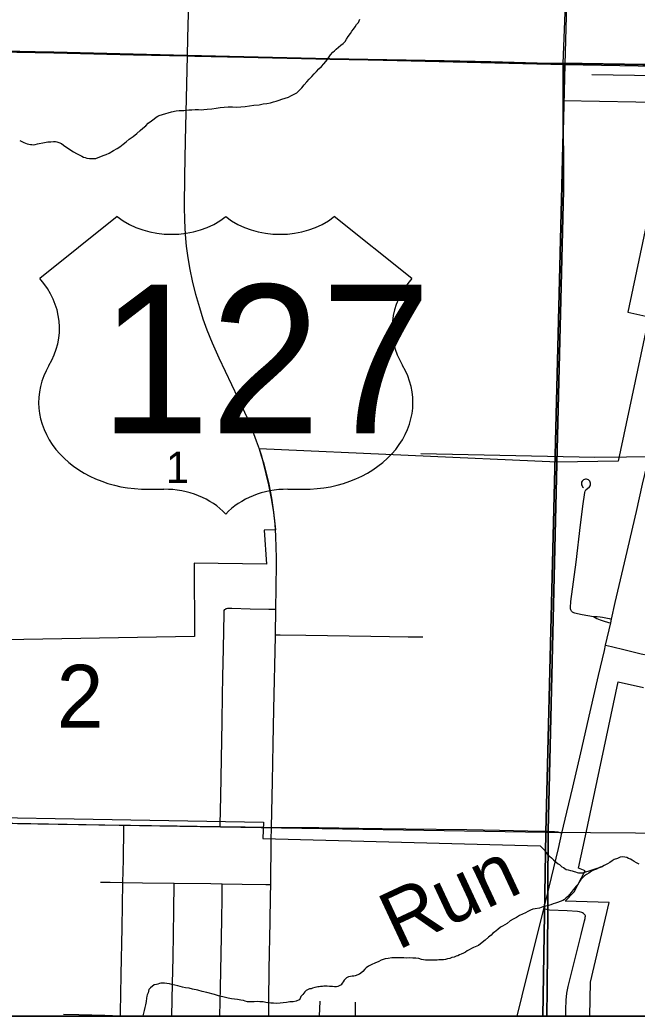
# Model space of a CAD drawing. Extents: x 2.4 to 73.1, y 4.5 to 25.6.
# Drawn here: x 30.055 to 30.465, y 17.985 to 18.648 of the extents above; entities that cross this region are included whole.
import ezdxf

# ---------------------------------------------------------------- set-up
doc = ezdxf.new("R2010")
doc.units = 0
for name, color, linetype in [('GM_X_City_Street', 7, 'Continuous'), ('GM_X_Corporation', 7, 'Continuous'), ('GM_X_County_Road', 7, 'Continuous'), ('GM_X_Interchange_Ramps', 7, 'Continuous'), ('GM_X_Minor_Lake_Text', 7, 'Continuous'), ('GM_X_Minor_River', 7, 'Continuous'), ('GM_X_Section', 7, 'Continuous'), ('GM_X_Section_Text', 7, 'Continuous'), ('GM_X_State_Route', 7, 'Continuous'), ('GM_X_Township', 7, 'Continuous'), ('GM_X_Township_Road', 7, 'Continuous'), ('GM_X_US_Location', 7, 'Continuous'), ('GM_X_US_Route', 7, 'Continuous'), ('GM_X_US_Shield', 7, 'Continuous'), ('SH_Cut_Line', 7, 'Continuous'), ('SH_Data', 7, 'Continuous')]:
    doc.layers.add(name, color=color, linetype=linetype)

msp = doc.modelspace()

# ---------------------------------------------------------------- linework, layer by layer
at = {"layer": 'GM_X_City_Street'}
msp.add_line((30.25423, 17.98522), (30.25469, 17.99511), dxfattribs=at)
for points in [[(30.22492, 18.23874), (30.22801, 18.23869), (30.24502, 18.23843), (30.28833, 18.23777), (30.31308, 18.23744), (30.31926, 18.23746), (30.32297, 18.2375)], [(30.1219, 17.98541), (30.12195, 17.98798), (30.12215, 17.99963), (30.12239, 18.01287), (30.12298, 18.044), (30.12345, 18.07399), (30.12383, 18.08914), (30.12413, 18.11017), (30.12416, 18.11215)], [(30.10852, 18.07435), (30.11513, 18.07422), (30.12345, 18.07399), (30.13663, 18.07375), (30.15751, 18.07349), (30.18191, 18.0733), (30.18958, 18.07321), (30.20277, 18.07302), (30.21857, 18.07279), (30.22175, 18.07275)], [(30.1561, 17.98522), (30.15657, 18.00694), (30.15681, 18.02407), (30.15747, 18.05518), (30.15751, 18.07349)], [(30.18797, 17.98522), (30.18797, 17.98527), (30.18829, 18.00397), (30.18921, 18.04913), (30.18944, 18.06393), (30.18958, 18.07321)], [(30.41797, 17.98522), (30.41805, 17.98956), (30.41822, 17.99576), (30.41867, 18.00038), (30.41948, 18.00496), (30.42823, 18.03952), (30.4304, 18.04856), (30.43074, 18.05003), (30.4309, 18.05115), (30.43093, 18.05148), (30.43092, 18.05179), (30.4308, 18.05229), (30.43063, 18.05263), (30.43041, 18.05287), (30.4298, 18.05342), (30.42908, 18.05384), (30.4285, 18.05412), (30.42709, 18.05458), (30.42561, 18.05483), (30.41886, 18.05521), (30.40699, 18.05575), (30.40611, 18.05586), (30.40502, 18.05605), (30.40338, 18.05649)], [(30.27803, 17.98522), (30.27804, 17.98962), (30.27802, 17.99438)], [(30.08403, 17.98647), (30.09415, 17.98621), (30.11139, 17.98578), (30.1219, 17.98541), (30.12739, 17.98522)]]:
    msp.add_lwpolyline(points, dxfattribs=at)
at = {"layer": 'GM_X_Corporation'}
for points in [[(30.48071, 18.6179), (30.45695, 18.61824), (30.42882, 18.61865), (30.41612, 18.61875), (30.4162, 18.59398), (30.48874, 18.59276), (30.45921, 18.45328), (30.47306, 18.45009), (30.45278, 18.35426), (30.41211, 18.35353), (30.21409, 18.36248), (30.21556, 18.35786), (30.21641, 18.35521), (30.21695, 18.35328), (30.21869, 18.34615), (30.22042, 18.33883), (30.22222, 18.32961), (30.22367, 18.32033), (30.22457, 18.31256), (30.22484, 18.30853), (30.21749, 18.3083), (30.21891, 18.28563), (30.17097, 18.28643), (30.17102, 18.23759), (30.03215, 18.23516)], [(30.0279, 17.98522), (30.434, 17.98522), (30.4344, 18.00767), (30.44687, 18.06076), (30.4176, 18.06153), (30.42345, 18.06781), (30.43082, 18.0817), (30.42643, 18.08348), (30.431, 18.10507), (30.45269, 18.20758), (30.4695, 18.20371)]]:
    msp.add_lwpolyline(points, dxfattribs=at)
at = {"layer": 'GM_X_County_Road'}
msp.add_line((30.44442, 18.23188), (30.44778, 18.24662), dxfattribs=at)
for points in [[(30.44778, 18.24662), (30.44836, 18.24915), (30.45086, 18.26013), (30.45782, 18.29042), (30.46485, 18.32069), (30.46894, 18.33889), (30.47334, 18.35731), (30.47396, 18.35999)], [(30.41537, 18.10676), (30.41868, 18.12084), (30.42252, 18.1375), (30.42794, 18.16016), (30.43411, 18.18745), (30.43973, 18.21166), (30.44361, 18.22831), (30.44442, 18.23188)], [(29.99456, 18.11418), (30.00252, 18.11405), (30.0134, 18.11395), (30.03829, 18.11363), (30.07407, 18.11307), (30.12416, 18.11215)], [(30.12416, 18.11215), (30.1285, 18.11207), (30.1425, 18.11193), (30.15961, 18.11162), (30.18606, 18.11139), (30.18817, 18.11135)], [(30.18817, 18.11135), (30.20472, 18.11103), (30.21561, 18.11092), (30.21717, 18.11086), (30.22234, 18.11068)], [(30.40338, 18.05649), (30.40618, 18.06806), (30.40688, 18.07094), (30.413, 18.09663), (30.41537, 18.10676)], [(30.38559, 17.98522), (30.3923, 18.01211), (30.39872, 18.03773), (30.40338, 18.05649)]]:
    msp.add_lwpolyline(points, dxfattribs=at)
at = {"layer": 'GM_X_Interchange_Ramps'}
for points in [[(29.49738, 21.67933), (29.49738, 18.64027), (29.51045, 18.6399), (29.59434, 18.63772), (29.6596, 18.63611), (29.71864, 18.63468), (29.75282, 18.63393), (29.80409, 18.63267), (29.84759, 18.63174), (29.91284, 18.62996), (30.01539, 18.62763), (30.04024, 18.62677), (30.07753, 18.62611), (30.13036, 18.62476), (30.1663, 18.62397), (30.17131, 18.62386), (30.20382, 18.62314), (30.26115, 18.6218), (30.33704, 18.62041), (30.36807, 18.61966), (30.40672, 18.61876), (30.41612, 18.61875), (30.43582, 19.1212)], [(29.49738, 17.98522), (30.40528, 17.98522), (30.40547, 18.0034), (30.40599, 18.05614), (30.40606, 18.06834), (30.40631, 18.10839), (30.4123, 18.36171), (30.41639, 18.53419), (30.4162, 18.59398), (30.41612, 18.61875), (30.40672, 18.61876), (30.36807, 18.61966), (30.33704, 18.62041), (30.26115, 18.6218), (30.20382, 18.62314), (30.17131, 18.62386), (30.1663, 18.62397), (30.13036, 18.62476), (30.07753, 18.62611), (30.04024, 18.62677)], [(30.48071, 18.6179), (30.45695, 18.61824), (30.42882, 18.61865), (30.41612, 18.61875), (30.4162, 18.59398), (30.41639, 18.53419), (30.4123, 18.36171), (30.40631, 18.10839), (30.40606, 18.06834), (30.40599, 18.05614), (30.40547, 18.0034), (30.40528, 17.98522), (33.45306, 17.98522)]]:
    msp.add_lwpolyline(points, dxfattribs=at)
at = {"layer": 'GM_X_Minor_River'}
for points in [[(30.14975, 18.58474), (30.15588, 18.5865), (30.15894, 18.58719), (30.16084, 18.58733), (30.16236, 18.5873), (30.16407, 18.58745), (30.16579, 18.5876), (30.16731, 18.58776), (30.16941, 18.5879), (30.1715, 18.58804), (30.17378, 18.58799), (30.17549, 18.58795), (30.1774, 18.5881), (30.17949, 18.58824), (30.18273, 18.58855), (30.1854, 18.58887), (30.18807, 18.58938), (30.19074, 18.5897), (30.19359, 18.58982), (30.19625, 18.58976), (30.1991, 18.5897), (30.20196, 18.58982), (30.20482, 18.59014), (30.20768, 18.59045), (30.21054, 18.59096), (30.21416, 18.59125), (30.21683, 18.59176), (30.21912, 18.59209), (30.2216, 18.59261), (30.22352, 18.59313), (30.22543, 18.59366), (30.22735, 18.59438), (30.22926, 18.5949), (30.23137, 18.59561), (30.23348, 18.59632), (30.2352, 18.59705), (30.23694, 18.59815), (30.23905, 18.59924), (30.24061, 18.60072), (30.24236, 18.60258), (30.24392, 18.60445), (30.24568, 18.60649), (30.24743, 18.60835), (30.24918, 18.61002), (30.25074, 18.6117), (30.2523, 18.61337), (30.25386, 18.61505), (30.25542, 18.61672), (30.25717, 18.61839), (30.25834, 18.61988), (30.25932, 18.62119), (30.26148, 18.62437), (30.26305, 18.62623), (30.26421, 18.62716), (30.26537, 18.62827), (30.26692, 18.62956), (30.26828, 18.63086), (30.27002, 18.63196), (30.27119, 18.63327), (30.27217, 18.63476), (30.27336, 18.63663), (30.27473, 18.6385), (30.27572, 18.64019), (30.2767, 18.6415), (30.27787, 18.64299), (30.27886, 18.64449), (30.28003, 18.64598), (30.28103, 18.64805)], [(30.43533, 18.61131), (31.49498, 18.59472)], [(30.05488, 18.5675), (30.05639, 18.56671), (30.0577, 18.56611), (30.05864, 18.56571), (30.05978, 18.56531), (30.06091, 18.56509), (30.06205, 18.56488), (30.063, 18.56485), (30.06413, 18.56464), (30.06509, 18.56481), (30.06662, 18.56534), (30.07139, 18.56618), (30.07349, 18.56652), (30.07558, 18.56666), (30.0773, 18.56681), (30.07863, 18.56678), (30.07958, 18.56657), (30.0809, 18.56616), (30.08259, 18.56536), (30.08409, 18.56438), (30.08558, 18.5632), (30.08727, 18.56203), (30.08896, 18.56104), (30.09064, 18.55986), (30.09271, 18.55886), (30.0944, 18.55788), (30.09609, 18.55708), (30.09741, 18.55648), (30.09835, 18.55608), (30.09948, 18.55567), (30.10138, 18.55544), (30.1029, 18.55541), (30.10442, 18.55556), (30.10556, 18.55554), (30.10709, 18.55607), (30.10882, 18.55679), (30.11036, 18.55752), (30.11228, 18.55823), (30.11439, 18.55913), (30.11728, 18.56078), (30.11959, 18.56206), (30.12152, 18.56334), (30.12365, 18.565), (30.12558, 18.56648), (30.12771, 18.56833), (30.13023, 18.57017), (30.13274, 18.5722), (30.13487, 18.57406), (30.13681, 18.57572), (30.13875, 18.5772), (30.14031, 18.57906), (30.14244, 18.58053), (30.14418, 18.58182), (30.14553, 18.58293), (30.14669, 18.58366), (30.14765, 18.58402), (30.14975, 18.58474)], [(30.32148, 18.35921), (30.43721, 18.35696), (30.68973, 18.35957), (30.7177, 18.31848), (30.77838, 18.31995), (30.82527, 18.29172), (30.87479, 18.30408), (30.90304, 18.31768), (30.91765, 18.32222)], [(29.91477, 18.1194), (30.21692, 18.1141), (30.21649, 18.10329), (30.40097, 18.09835)], [(30.40097, 18.09835), (30.40376, 18.09563), (30.40579, 18.09273), (30.40728, 18.09137), (30.4084, 18.09039), (30.4097, 18.08903), (30.41156, 18.08747), (30.41287, 18.08649), (30.41381, 18.0859), (30.4153, 18.08454), (30.41642, 18.08394), (30.41811, 18.08276), (30.41944, 18.08254), (30.42113, 18.08193), (30.42227, 18.08172), (30.4234, 18.08131), (30.42435, 18.0811), (30.42548, 18.0807), (30.42642, 18.08049), (30.42794, 18.08045), (30.42927, 18.08042), (30.4423, 18.08468)], [(30.46667, 18.08622), (30.46498, 18.08721), (30.46347, 18.088), (30.46216, 18.08879), (30.46104, 18.08957), (30.45972, 18.08998), (30.4584, 18.09058), (30.45726, 18.0908), (30.45556, 18.09103), (30.45403, 18.09087), (30.4523, 18.08996), (30.45019, 18.08925), (30.44865, 18.08834), (30.44711, 18.08742), (30.44557, 18.08651), (30.44441, 18.08577), (30.44345, 18.08542), (30.4423, 18.08468)], [(30.4423, 18.08468), (30.44076, 18.08415), (30.43826, 18.08288), (30.43712, 18.08252), (30.43596, 18.08198), (30.435, 18.08162), (30.43326, 18.08033), (30.43172, 18.07941), (30.43037, 18.0785), (30.42784, 18.07608), (30.42666, 18.07402), (30.42587, 18.07271), (30.42489, 18.07159), (30.42392, 18.07048), (30.42275, 18.06917), (30.42157, 18.06749), (30.42039, 18.066), (30.41922, 18.0647), (30.41806, 18.06358), (30.41709, 18.06284), (30.41593, 18.06211), (30.41421, 18.06139), (30.41248, 18.06067), (30.41114, 18.06032), (30.40961, 18.05979), (30.40807, 18.05925), (30.40635, 18.05872), (30.40463, 18.05838), (30.40272, 18.05785), (30.40042, 18.05696), (30.39756, 18.05664), (30.39603, 18.0563), (30.3945, 18.05557), (30.39277, 18.05485), (30.39104, 18.05394), (30.38912, 18.05303), (30.38719, 18.05213), (30.38507, 18.05085), (30.38296, 18.04976), (30.38103, 18.04847), (30.3789, 18.04681), (30.37582, 18.04498), (30.37447, 18.04425), (30.37273, 18.04277), (30.37156, 18.04185), (30.3706, 18.04111), (30.36944, 18.04038), (30.36827, 18.03907), (30.36653, 18.03759), (30.36439, 18.03574), (30.36226, 18.03408), (30.35994, 18.03223), (30.35764, 18.03134), (30.35649, 18.03079), (30.35244, 18.02861), (30.35128, 18.02768), (30.34994, 18.02695), (30.3484, 18.02642), (30.34725, 18.02588), (30.3461, 18.02533), (30.34514, 18.02497), (30.3438, 18.02443), (30.34208, 18.02409), (30.34093, 18.02355), (30.3394, 18.0232), (30.33787, 18.02286), (30.33653, 18.0227), (30.33539, 18.02254), (30.33444, 18.02256), (30.33349, 18.02258), (30.33234, 18.02241), (30.33082, 18.02245), (30.3295, 18.02248), (30.32816, 18.02232), (30.32683, 18.02235), (30.32588, 18.02237), (30.32474, 18.0224), (30.32341, 18.02262), (30.3219, 18.02284), (30.3202, 18.02345), (30.3183, 18.02368), (30.31621, 18.02373), (30.31375, 18.02398), (30.31203, 18.02382), (30.31032, 18.02386), (30.3088, 18.0239), (30.30728, 18.02393), (30.305, 18.02398), (30.30234, 18.02385), (30.29986, 18.02353), (30.29795, 18.02319), (30.29642, 18.02285), (30.29528, 18.0225), (30.29354, 18.02158), (30.29105, 18.0205), (30.28893, 18.01941), (30.28682, 18.01832), (30.28528, 18.0174), (30.2843, 18.01648), (30.28294, 18.0148), (30.28177, 18.01368)], [(30.28177, 18.01368), (30.28081, 18.01314), (30.27793, 18.01187), (30.27697, 18.0117), (30.27602, 18.01172), (30.27488, 18.01156), (30.27354, 18.0114), (30.2722, 18.01067), (30.27064, 18.009), (30.26986, 18.00807), (30.26927, 18.00713), (30.26867, 18.006), (30.26771, 18.00546), (30.26636, 18.00492), (30.26541, 18.00475), (30.26427, 18.00477), (30.26275, 18.00481), (30.26085, 18.00485), (30.25933, 18.00507), (30.25838, 18.0051), (30.25705, 18.00513), (30.2561, 18.00496), (30.25496, 18.00479), (30.254, 18.00463), (30.25305, 18.00465), (30.2521, 18.00448), (30.25114, 18.00431), (30.24961, 18.00378), (30.24865, 18.00342), (30.24751, 18.00325), (30.24539, 18.00216), (30.24442, 18.00124), (30.24305, 17.99956), (30.24188, 17.99825), (30.24128, 17.99694), (30.24069, 17.996), (30.23877, 17.99509), (30.23667, 17.99476), (30.23458, 17.99462), (30.23229, 17.99429), (30.22581, 17.99368), (30.22372, 17.99373), (30.22182, 17.99377), (30.21992, 17.994), (30.21841, 17.99423), (30.21671, 17.99464), (30.21443, 17.9947), (30.21272, 17.99492), (30.21082, 17.99478), (30.20948, 17.99462), (30.20853, 17.99464), (30.20739, 17.99466), (30.20644, 17.99469), (30.20474, 17.9951), (30.20361, 17.99551), (30.2019, 17.99574), (30.19963, 17.99617), (30.19774, 17.9964), (30.19565, 17.99664), (30.19357, 17.99707), (30.19168, 17.99749), (30.18714, 17.99873), (30.1845, 17.99955), (30.1792, 18.00081), (30.17618, 18.00164), (30.17335, 18.00246), (30.16975, 18.00311), (30.16748, 18.00373), (30.16521, 18.00397), (30.16313, 18.0044), (30.16161, 18.00482), (30.15991, 18.00523), (30.15802, 18.00566), (30.15613, 18.00627), (30.15443, 18.00669), (30.15273, 18.00691), (30.15121, 18.00714), (30.14988, 18.00717), (30.14874, 18.007), (30.14778, 18.00684), (30.14682, 18.00648), (30.14587, 18.00631), (30.14434, 18.00596), (30.14182, 18.00393), (30.14066, 18.00282), (30.14023, 18.00074), (30.13963, 17.99942), (30.13942, 17.99848), (30.1392, 17.99715), (30.13896, 17.99488), (30.13853, 17.99261), (30.13811, 17.99091), (30.13769, 17.98902), (30.13726, 17.98713), (30.13685, 17.98543), (30.13681, 17.98522)]]:
    msp.add_lwpolyline(points, dxfattribs=at)
at = {"layer": 'GM_X_Section'}
for points in [[(29.92965, 19.13465), (30.43117, 19.12128), (30.41719, 18.61809), (29.91527, 18.62994)], [(30.86803, 19.11145), (30.43117, 19.12128), (30.41719, 18.61809), (30.9167, 18.60894), (30.95137, 18.60852), (30.95403, 18.77027), (30.86803, 18.77027)], [(29.91527, 18.62994), (30.41719, 18.61809), (30.40456, 18.10728), (29.90446, 18.11549)], [(30.9167, 18.60894), (30.91045, 18.10349), (30.40456, 18.10728), (30.41719, 18.61809)]]:
    msp.add_lwpolyline(points, close=True, dxfattribs=at)
at = {"layer": 'GM_X_State_Route'}
msp.add_line((30.22492, 18.23874), (30.2252, 18.25576), dxfattribs=at)
for points in [[(30.16642, 18.6237), (30.16663, 18.63553), (30.16795, 18.68526), (30.16868, 18.70546), (30.17039, 18.77073), (30.17181, 18.8189), (30.17292, 18.85619), (30.17375, 18.88727), (30.17457, 18.91836), (30.17747, 19.01781), (30.17859, 19.0551), (30.17994, 19.10328), (30.18067, 19.12692)], [(30.21421, 18.3622), (30.21239, 18.3675), (30.20965, 18.37476), (30.20603, 18.38333), (30.20017, 18.39602), (30.18755, 18.42274), (30.18312, 18.43269), (30.17958, 18.44134), (30.17692, 18.44866), (30.17456, 18.45608), (30.17202, 18.46507), (30.16978, 18.47414), (30.1682, 18.48177), (30.1669, 18.48945), (30.16589, 18.49718), (30.16518, 18.50494), (30.16467, 18.51427), (30.16448, 18.52361), (30.16458, 18.54383), (30.16512, 18.56714), (30.16642, 18.6237)], [(30.22496, 18.30825), (30.22469, 18.31228), (30.22379, 18.32005), (30.22233, 18.32934), (30.22054, 18.33856), (30.2188, 18.34587), (30.21706, 18.353), (30.21653, 18.35493), (30.21568, 18.35758), (30.21421, 18.3622)], [(30.2252, 18.25576), (30.2253, 18.27004), (30.22544, 18.27283), (30.22557, 18.28316), (30.22559, 18.29028), (30.22546, 18.29666), (30.22522, 18.30448), (30.22496, 18.30825)], [(30.22234, 18.11068), (30.22258, 18.12095), (30.223, 18.14118), (30.2235, 18.16606), (30.22389, 18.1894), (30.22491, 18.23762), (30.22492, 18.23874)], [(30.22175, 18.07275), (30.22215, 18.10229), (30.22234, 18.11068)], [(30.22084, 18.0164), (30.22135, 18.04784), (30.22164, 18.06495), (30.22175, 18.07275)], [(30.22056, 17.98522), (30.22049, 17.99494), (30.22084, 18.0164)]]:
    msp.add_lwpolyline(points, dxfattribs=at)
at = {"layer": 'GM_X_Township'}
msp.add_lwpolyline([(30.92238, 18.60883), (30.91795, 18.60896), (30.91319, 18.60918), (30.88149, 18.60963), (30.84568, 18.61038), (30.79587, 18.6118), (30.77562, 18.61225), (30.71802, 18.61361), (30.68042, 18.61425), (30.66974, 18.61443), (30.66506, 18.61447), (30.64585, 18.61492), (30.61649, 18.61538), (30.59168, 18.61575), (30.54215, 18.61671), (30.53414, 18.61696), (30.52498, 18.61726), (30.48071, 18.6179), (30.45695, 18.61824), (30.42882, 18.61865), (30.41612, 18.61875), (30.43582, 19.1212)], dxfattribs=at)
at = {"layer": 'GM_X_Township_Road'}
for points in [[(29.49738, 18.64), (29.51057, 18.63963), (29.59446, 18.63745), (29.65971, 18.63583), (29.71875, 18.63441), (29.75294, 18.63366), (29.8042, 18.63239), (29.84771, 18.63147), (29.91296, 18.62968), (30.01551, 18.62736), (30.04036, 18.62649), (30.07765, 18.62583), (30.13047, 18.62448), (30.16642, 18.6237)], [(30.16642, 18.6237), (30.17143, 18.62358), (30.20394, 18.62286), (30.26127, 18.62153), (30.33715, 18.62013), (30.36819, 18.61939), (30.40683, 18.61849), (30.41624, 18.61848)], [(30.41624, 18.61848), (30.42894, 18.61837), (30.45707, 18.61797), (30.48083, 18.61762), (30.5251, 18.61698), (30.53426, 18.61669)], [(30.42176, 18.25446), (30.42145, 18.25489), (30.42125, 18.25544), (30.42105, 18.25613), (30.42101, 18.25655), (30.42098, 18.25702), (30.42131, 18.26087), (30.42473, 18.28712), (30.42778, 18.31183), (30.4295, 18.32574), (30.43035, 18.33192), (30.43064, 18.33349), (30.43091, 18.33436), (30.43131, 18.33508), (30.43366, 18.33717), (30.43408, 18.33773), (30.43431, 18.33834), (30.43442, 18.33901), (30.4344, 18.33966), (30.43424, 18.34032), (30.43391, 18.34092), (30.43351, 18.34141), (30.43294, 18.34183), (30.43234, 18.3421), (30.43166, 18.34224), (30.43097, 18.34225), (30.4303, 18.3421), (30.42966, 18.34184), (30.42915, 18.34145), (30.42873, 18.34099), (30.42842, 18.34035), (30.4283, 18.33971), (30.42832, 18.33904), (30.42846, 18.33838), (30.42877, 18.33773), (30.42912, 18.33718), (30.42963, 18.3366)], [(30.19126, 18.2555), (30.19164, 18.25584), (30.19214, 18.25615), (30.19267, 18.2563), (30.19335, 18.2564), (30.19592, 18.25639), (30.20819, 18.25604), (30.22047, 18.25584), (30.2252, 18.25576)], [(30.18817, 18.11135), (30.1882, 18.11292), (30.18851, 18.13116), (30.18941, 18.18116), (30.1898, 18.19834), (30.18993, 18.21084), (30.19027, 18.22959), (30.19073, 18.25299), (30.19081, 18.25421), (30.19092, 18.25485), (30.19126, 18.2555)], [(30.42176, 18.25446), (30.42221, 18.25411), (30.42263, 18.25383), (30.42304, 18.25368), (30.42375, 18.25345), (30.42887, 18.25231), (30.43635, 18.25083)], [(30.43635, 18.25083), (30.43857, 18.24963), (30.44077, 18.24872), (30.44279, 18.24797), (30.4463, 18.24702), (30.44778, 18.24662)], [(30.43635, 18.25083), (30.43885, 18.25082), (30.44077, 18.25064), (30.44244, 18.25049), (30.44677, 18.24951), (30.44836, 18.24915)], [(30.44442, 18.23188), (30.44833, 18.23094), (30.45745, 18.22875), (30.46804, 18.22617), (30.47261, 18.2253), (30.47721, 18.22476), (30.47802, 18.22481)], [(29.99456, 18.11418), (30.00252, 18.11405), (30.0134, 18.11395), (30.03829, 18.11363), (30.07407, 18.11307), (30.12416, 18.11215)], [(30.12416, 18.11215), (30.1285, 18.11207), (30.1425, 18.11193), (30.15961, 18.11162), (30.18606, 18.11139), (30.18817, 18.11135)], [(30.18817, 18.11135), (30.20472, 18.11103), (30.21561, 18.11092), (30.21717, 18.11086), (30.22234, 18.11068)], [(30.22234, 18.11068), (30.25385, 18.11052), (30.28036, 18.11011), (30.31156, 18.10981), (30.35211, 18.10924), (30.37394, 18.10882), (30.40201, 18.10826), (30.40642, 18.10812), (30.41048, 18.10798), (30.41253, 18.10768), (30.41387, 18.10729), (30.41537, 18.10676)]]:
    msp.add_lwpolyline(points, dxfattribs=at)
at = {"layer": 'GM_X_US_Route'}
msp.add_line((30.22492, 18.23874), (30.2252, 18.25576), dxfattribs=at)
for points in [[(30.16642, 18.6237), (30.16663, 18.63553), (30.16795, 18.68526), (30.16868, 18.70546), (30.17039, 18.77073), (30.17181, 18.8189), (30.17292, 18.85619), (30.17375, 18.88727), (30.17457, 18.91836), (30.17747, 19.01781), (30.17859, 19.0551), (30.17994, 19.10328), (30.18067, 19.12692)], [(30.21421, 18.3622), (30.21239, 18.3675), (30.20965, 18.37476), (30.20603, 18.38333), (30.20017, 18.39602), (30.18755, 18.42274), (30.18312, 18.43269), (30.17958, 18.44134), (30.17692, 18.44866), (30.17456, 18.45608), (30.17202, 18.46507), (30.16978, 18.47414), (30.1682, 18.48177), (30.1669, 18.48945), (30.16589, 18.49718), (30.16518, 18.50494), (30.16467, 18.51427), (30.16448, 18.52361), (30.16458, 18.54383), (30.16512, 18.56714), (30.16642, 18.6237)], [(30.22496, 18.30825), (30.22469, 18.31228), (30.22379, 18.32005), (30.22233, 18.32934), (30.22054, 18.33856), (30.2188, 18.34587), (30.21706, 18.353), (30.21653, 18.35493), (30.21568, 18.35758), (30.21421, 18.3622)], [(30.2252, 18.25576), (30.2253, 18.27004), (30.22544, 18.27283), (30.22557, 18.28316), (30.22559, 18.29028), (30.22546, 18.29666), (30.22522, 18.30448), (30.22496, 18.30825)], [(30.22234, 18.11068), (30.22258, 18.12095), (30.223, 18.14118), (30.2235, 18.16606), (30.22389, 18.1894), (30.22491, 18.23762), (30.22492, 18.23874)], [(30.22175, 18.07275), (30.22215, 18.10229), (30.22234, 18.11068)], [(30.22084, 18.0164), (30.22135, 18.04784), (30.22164, 18.06495), (30.22175, 18.07275)], [(30.22056, 17.98522), (30.22049, 17.99494), (30.22084, 18.0164)]]:
    msp.add_lwpolyline(points, dxfattribs=at)
at = {"layer": 'GM_X_US_Shield'}
for p, q in [((30.11979, 18.51684), (30.06829, 18.47564)), ((30.31549, 18.47564), (30.26399, 18.51684)), ((30.14039, 18.33556), (30.15069, 18.33556)), ((30.23309, 18.33556), (30.24339, 18.33556))]:
    msp.add_line(p, q, dxfattribs=at)
for points in [[(29.90227, 17.98522), (30.4027, 17.98522), (30.40456, 18.10728), (29.90446, 18.11549)], [(30.4027, 17.98522), (30.90891, 17.98522), (30.91045, 18.10349), (30.40456, 18.10728)]]:
    msp.add_lwpolyline(points, close=True, dxfattribs=at)
for centre, major_axis, start_param, end_param in [((30.15584, 18.54626), (-0.0515, 0), 0.795399, 2.346194), ((30.22794, 18.54626), (-0.0515, 0), 0.795399, 2.346194), ((30.00924, 18.44255), (0.0721, 0), 5.838949, 6.894067), ((30.37455, 18.44255), (-0.0721, 0), 5.672304, 6.727422), ((30.13959, 18.39324), (0.0721, 0), 2.702327, 4.723529), ((30.24419, 18.39324), (-0.0721, 0), 1.559657, 3.580859), ((30.15069, 18.29436), (-0.0515, 0), 3.785094, 4.712389), ((30.23309, 18.29436), (-0.0515, 0), 4.712389, 5.639684)]:
    msp.add_ellipse(centre, major_axis=major_axis, ratio=0.8, start_param=start_param, end_param=end_param, dxfattribs=at)
at = {"layer": 'SH_Cut_Line'}
msp.add_lwpolyline([(29.49738, 21.67933), (29.49738, 17.98522), (36.29738, 17.98522), (36.29738, 20.02567)], dxfattribs=at)
at = {"layer": 'SH_Data'}
msp.add_lwpolyline([(29.49738, 24.78522), (36.29738, 24.78522), (36.29738, 17.98522), (29.49738, 17.98522)], close=True, dxfattribs=at)

# ---------------------------------------------------------------- texts
at = {"layer": 'GM_X_Minor_Lake_Text'}
msp.add_text('Run', height=0.037893, rotation=25.04016, dxfattribs=at).set_placement((30.30618, 18.0288))
at = {"layer": 'GM_X_Section_Text'}
for s, height, p in [('1', 0.02093, (30.15202, 18.33961)), ('2', 0.04186, (30.07945, 18.17692))]:
    msp.add_text(s, height=height, rotation=0.00001, dxfattribs=at).set_placement(p)
at = {"layer": 'GM_X_US_Location'}
for s, p in [('0', (30.19198, 18.42203)), ('/', (30.19199, 18.42203))]:
    msp.add_text(s, height=0.0000947, dxfattribs=at).set_placement(p)
msp.add_text('127', height=0.0000947, rotation=0.00001, dxfattribs=at).set_placement((30.16285, 18.40243))
at = {"layer": 'GM_X_US_Shield'}
msp.add_text('127', height=0.098877, dxfattribs=at).set_placement((30.10798, 18.37264))

doc.saveas('drawing.dxf')
